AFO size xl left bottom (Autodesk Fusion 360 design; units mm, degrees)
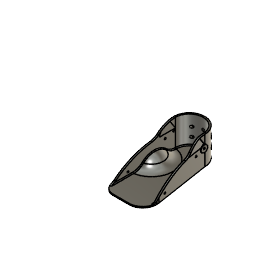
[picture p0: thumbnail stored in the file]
part number: 2025-10-02-12-56-12-317
parameter "d73" = 49
parameter "d131" = 16
sketch "Sketch1" plane through (0, 0, 0) normal (0, 0, 1) x axis (1, 0, 0)
  line L1 (28, -127.4) -> (-48, -127.4)
  line L2 (28, 0) -> (28, -127.4)
  line L3 (25, 0) -> (25, -127.4)
  line L4 (28, 0) -> (25, 0)
  line L5 (-18.603, -127.4) -> (-18.603, -115.6)
  line L6 (10.5, -127.4) -> (10.5, -109.9)
  line L7 (10.5, -127.4) -> (-18.603, -127.4)
  line L8 (36.7314, -101.9) -> (-43.9969, -101.9)
  line L9 (0, 0) -> (-28.984, 0)
  line L10 (-45, -127.4) -> (-25, 0)
  line L11 (-40.9969, -101.9) -> (-44.0794, -101.4161)
  line L12 (-48, -127.4) -> (-28, 0)
  line L13 (-43.6846, -101.9) -> (-43.6828, -102.2021)
  circle C1 centre (0, 0) radius 28
  circle C2 centre (0, 0) radius 25
  circle C3 centre (10.5, -109.9) radius 17.5
  circle C4 centre (-18.1846, -101.9) radius 22.5
  circle C5 centre (10.5, -109.9) radius 14.5
  circle C6 centre (-18.1846, -101.9) radius 25.5
  point P1 (0, 0)
  point P2 (0, 0)
  point P5 (28, 0)
  point P6 (0, 0)
  point P7 (25, 0)
  point P8 (25, -127.4)
  point P13 (-18.603, -127.4)
  point P11 (10.5, -109.9)
  point P14 (10.5, -109.9)
  point P15 (10.5, -127.4)
  point P20 (-25, 0)
  point P21 (-45, -127.4)
  point P22 (-40.9969, -101.9)
  point P10 (-18.1846, -101.9)
  point P25 (-28, 0)
  point P16 (-43.9969, -101.9)
  point P26 (-43.6828, -102.2021)
  point P27 (-43.6846, -101.9)
  point P19 (0, 0)
  coincident P1 P2
  coincident C1 P5
  tangent C1 L2
  perpendicular L1 L2
  coincident P1 P6
  vertical L3
  coincident C2 P7
  perpendicular L2 L4
  coincident L1 P8
  tangent L2 C3
  tangent L1 C3
  concentric C3 C5
  tangent L3 C5
  coincident L1 P13
  perpendicular L1 L5
  coincident P11 P14
  coincident L1 P15
  coincident C3 P15
  perpendicular L1 L6
  perpendicular L5 L8
  horizontal L9
  coincident C2 P20
  coincident L9 P20
  coincident L1 P21
  coincident L10 P22
  coincident L8 P22
  parallel L2 L3
  coincident P10 L8
  concentric C4 C6
  coincident L9 P25
  coincident C1 P25
  parallel L10 L12
  coincident P16 L12
  coincident C6 P26
  coincident L8 P27
  coincident C6 P27
  coincident P1 P19
  tangent L1 C6
  tangent C6 L12
  perpendicular L11 L12
  dimension "d2" diameter C1 = 56 (= "d57 + ( 3 * 2 ) * 1 mm")
  dimension "d4" distance P2 L1 = 127.4 (= "152.4 mm - 25 mm")
  dimension "d57" diameter C2 = 50
  dimension "d74" diameter C3 = 35
  dimension "d252" diameter C4 = 45 (= "d73 - 4 mm")
  dimension "d322" distance P8 P21 = 70
  dimension "d323" diameter C6 = 51 (= "d252 + 6 mm")
extrude "Extrude1" new body sketch "Sketch1" profile of C1 L2 L3 L4 C3 L8 L9 L10 L11 C6 L12 along normal blind 35
extrude "Extrude2" add sketch "Sketch1" profile of C1 L1 L2 C2 L3 C3 C4 C5 L5 L6 L7 L8 L10 L11 C6 L13 along normal blind 3
extrude "Extrude15" new body sketch "Sketch1" profile of C1 C2 L4 L9 along normal blind 178
combine "Combine2"
work_plane "WorkPlane1" RotateAngle -90
fillet "Fillet69" radius 1 1
sketch "Sketch23" plane through (28, 0, 0) normal (1, 0, 0) x axis (0, 1, 0)
  line L1 (-28, 78) -> (0, 35)
  line L2 (-28, 178) -> (-28, 78)
  line L3 (0, 178) -> (-28, 178)
  line L4 (0, 35) -> (0, 178)
  circle C1 centre (-3, 143) radius 1.75
  point P5 (0, 178)
  point P6 (0, 178)
  point P2 (0, 35)
  point P8 (0, 35)
  point P4 (-28, 178)
  point P3 (-28, 78)
  point P7 (-3, 143)
  horizontal L3
  perpendicular L3 L4
  coincident P5 P6
  coincident P2 P8
  parallel L2 L4
  dimension "d253" distance P4 P5 = 28
  dimension "d254" distance P3 P4 = 100
  dimension "d255" diameter C1 = 3.5
  dimension "d256" distance L3 P7 = 35
  dimension "d257" distance L2 P7 = 25
extrude "Extrude18" add sketch "Sketch23" against normal blind 3
mirror "Mirror1" mirrorStitchTolerance 0.1
sketch "Sketch24" plane through (0, 16.0046, 10.4216) normal (0, -0.838, -0.5457) x axis (1, 0, 0)
  line L1 (-25, 80.6427) -> (-25, 29.3299)
  line L2 (-28, 80.6427) -> (-25, 80.6427)
  line L3 (-28, 29.3299) -> (-28, 80.6427)
  line L4 (-25, 62.182) -> (-28, 62.182)
  line L5 (-28, 30.2476) -> (-25, 30.2476)
  line L6 (-28, 30.2476) -> (-28, 62.182)
  line L7 (-25, 62.182) -> (-25, 30.2476)
  line L8 (-25, 29.3299) -> (-28, 29.3299)
  point P6 (-28, 62.182)
  point P7 (-25, 62.182)
  point P8 (-25, 30.2476)
  point P9 (-28, 30.2476)
  coincident L3 P6
  coincident L1 P7
  perpendicular L1 L4
  coincident L1 P8
  coincident L3 P9
  perpendicular L3 L5
sketch "Sketch25" plane through (0, 0, 35) normal (0, 0, 1) x axis (-1, 0, 0)
  line L1 (24.843, -1) -> (27.843, -1)
  line L2 (29.5678, 29.0967) -> (24.843, -1)
  line L3 (32.4956, 28.637) -> (29.5678, 29.0967)
  line L4 (32.4956, 28.637) -> (27.843, -1)
  line L5 (0, 0) -> (28.984, 0)
  line L6 (43.3761, 97.9455) -> (28, 0)
  line L7 (25, 0) -> (40.9969, 101.9)
  line L8 (28, 0) -> (25, 0)
  line L9 (40.9969, 101.9) -> (43.6811, 101.4786)
  arc A1 centre (18.1846, 101.9) radius 25.5 clockwise from (43.6811, 101.4786) to (43.3761, 97.9455)
  point P5 (32.4956, 28.637)
  point P4 (29.5678, 29.0967)
  point P15 (28, 0)
  point P8 (25, 0)
  point P2 (27.843, -1)
  horizontal L1
  coincident P5 L6
  coincident P4 L7
  coincident L4 P15
  coincident L2 P8
  perpendicular L3 L4
  dimension "d280" distance P2 P5 = 30
  dimension "d281" distance L1 L5 = 1
loft "Loft1" sketch "Sketch24" + "Sketch25"
sketch "Sketch26" plane through (0, 0, 35) normal (0, 0, 1) x axis (-1, 0, 0)
  line L1 (-28, 0) -> (-28, 101.9)
  line L2 (-25, 0) -> (-28, 0)
  line L3 (-28, -1) -> (-25, -1)
  line L4 (-28, -1) -> (-28, 29)
  line L5 (-25, 29) -> (-28, 29)
  line L6 (-25, -1) -> (-25, 29)
  line L7 (-28, 101.9) -> (-25, 101.9)
  line L8 (-25, 101.9) -> (-25, 0)
  point P5 (-28, -1)
  point P6 (-28, 29)
  point P7 (-25, 29)
  coincident L1 P5
  perpendicular L1 L3
  coincident L1 P6
  coincident P7 L8
  dimension "d278" distance P5 P6 = 30
  dimension "d279" distance L2 L3 = 1
sketch "Sketch27" plane through (0, 16.0046, 10.4216) normal (0, -0.838, -0.5457) x axis (1, 0, 0)
  line L1 (28, 80.6427) -> (28, 29.3299)
  line L2 (25, 80.6427) -> (28, 80.6427)
  line L3 (25, 29.3299) -> (25, 80.6427)
  line L4 (28, 29.3299) -> (25, 29.3299)
  line L5 (28, 63.1164) -> (25, 63.1164)
  line L6 (28, 32.1164) -> (28, 63.1164)
  line L7 (28, 32.1164) -> (25, 32.1164)
  line L8 (25, 63.1164) -> (25, 32.1164)
  point P6 (25, 63.1164)
  point P7 (28, 63.1164)
  point P8 (28, 32.1164)
  point P9 (25, 32.1164)
  coincident L3 P6
  coincident L1 P7
  perpendicular L1 L5
  coincident L1 P8
  coincident L3 P9
  perpendicular L6 L7
  dimension "d282" distance P7 P8 = 31
loft "Loft2" sketch "Sketch27" + "Sketch26"
work_plane "WorkPlane4" AlongDistance 28 (= "25 mm + 3 mm")
sketch "Sketch9" plane through (0, 28, 0) normal (0, 1, 0) x axis (1, 0, 0)
  circle C1 centre (0, -16) radius 2.25
  circle C2 centre (0, -32) radius 2.25
  circle C3 centre (0, -64) radius 2.25
  circle C4 centre (0, -96) radius 2.25
  circle C5 centre (0, -80) radius 2.25
  circle C6 centre (0, -112) radius 2.25
  circle C7 centre (0, -128) radius 2.25
  circle C8 centre (0, -144) radius 2.25
  point P2 (0, -16)
  point P7 (0, 0)
  point P3 (0, -32)
  point P4 (0, -64)
  point P6 (0, -80)
  point P5 (0, -96)
  point P8 (0, -112)
  point P9 (0, -128)
  point P10 (0, -144)
  dimension "d123" diameter C1 = 4.5
  dimension "d124" diameter C2 = 4.5
  dimension "d126" diameter C3 = 4.5
  dimension "d127" diameter C4 = 4.5
  dimension "d128" diameter C5 = 4.5
  dimension "d129" distance P2 P7 = 16
  dimension "d130" distance P2 P3 = 16
  dimension "d133" distance P4 P6 = 16 (= "d131")
  dimension "d134" distance P5 P6 = 16 (= "d131")
  dimension "d291" diameter C6 = 4.5
  dimension "d292" distance P5 P8 = 16 (= "d131")
  dimension "d293" distance P8 P9 = 16 (= "d130")
  dimension "d294" diameter C7 = 4.5
  dimension "d295" diameter C8 = 4.5
  dimension "d296" distance P9 P10 = 16 (= "d131")
extrude "Extrude20" cut sketch "Sketch9" against normal blind 30
path_pattern "PathPattern3" PathPatternDelta 88.0394
fillet "Fillet51" radius 7 15
fillet "Fillet52" radius 130 130
sphere_primitive "SpherePrimitive3" Diameter 55
move_face "MoveFace3"
boundary_fill "BoundaryFill2"
offset_faces "OffsetFaces2" distance 3
shell "Shell7" innerThickness 2.99
fillet "Fillet74" radius 10 15
hole "Hole6" HoleDepth 106.033 HoleDiameter 3.5 TipAngle 118
hole "Hole7" HoleDepth 106.033 HoleDiameter 3.5 TipAngle 118
work_plane "WorkPlane5" AlongDistance 100
work_plane "WorkPlane6" AlongDistance 51.6037
fillet "Fillet76" radius 30
fillet "Fillet79" radius 25
fillet "Fillet83" radius 22
fillet "Fillet85" radius 30 30
fillet "Fillet86" radius 45
split "Split1"
work_plane "WorkPlane7" AlongDistance -28 (= "-( 56 / 2 ) * 1 mm")
sketch "Sketch35" plane through (-28, 0, 0) normal (1, 0, 0) x axis (0, 1, 0)
  circle C1 centre (-2.7874, 31.4508) radius 6
  dimension "d426" diameter C1 = 12
extrude "Extrude22" add sketch "Sketch35" against normal blind 2
fillet "Fillet87" radius 35
sketch "Sketch33" plane through (27.99, 0, 0) normal (1, 0, 0) x axis (0, 1, 0)
  line L1 (0, 139.3302) -> (0, 52.395)
  line L2 (0, 175.01) -> (0, 146.6698)
  line L3 (-11.056, 175.01) -> (0, 175.01)
  line L4 (-25.01, 78.8877) -> (-25.01, 161.056)
  line L5 (-15.1078, 63.6808) -> (-25.01, 78.8877)
  line L6 (-16.1988, 60.7566) -> (-15.1078, 63.6808)
  line L7 (2, 178) -> (28, 178)
  arc A1 centre (7.4005, 86.6037) radius 35 clockwise from (0, 52.395) to (-16.1988, 60.7566)
  arc A2 centre (-3, 143) radius 4.74 clockwise from (0, 139.3302) to (0, 146.6698)
  arc A3 centre (2, 148) radius 30 clockwise from (-25.01, 161.056) to (-11.056, 175.01)
  circle C1 centre (-3, 128) radius 1.5
  circle C2 centre (-3, 98) radius 1.7185
  circle C3 centre (-3, 32) radius 1.75
  point P16 (-3, 128)
  point P17 (-3, 98)
  point P18 (-3, 32)
  vertical P16 P17
  vertical P17 P18
  dimension "d413" diameter C1 = 3
  dimension "d414" distance P16 P17 = 30
  dimension "d415" diameter C3 = 3.5
  dimension "d416" distance P17 P18 = 66
  dimension "d417" distance P16 L7 = 50
  dimension "d418" distance L1 P16 = 3
extrude "Extrude21" cut sketch "Sketch33" profile of C1 C2 C3 against normal blind 133.937
fillet "Fillet88" radius 36
sketch "Sketch37" plane through (-28, 0, 0) normal (1, 0, 0) x axis (0, 1, 0)
fillet "Fillet98" radius 48
fillet "Fillet99" radius 48
sketch "Sketch38" plane through (-28, 0, 0) normal (1, 0, 0) x axis (0, 1, 0)
  line L1 (-5.5406, 132.8689) -> (0, 132.8689)
  line L2 (-5.5406, 93.572) -> (-5.5406, 132.8689)
  line L3 (0, 93.572) -> (-5.5406, 93.572)
  line L4 (0, 132.8689) -> (0, 93.572)
  horizontal L1
  vertical L2
  horizontal L3
  vertical L4
extrude "Extrude24" add sketch "Sketch38" along normal blind 1 and against normal blind 2
fillet "Fillet91" radius 2 2 2 2
fillet "Fillet92" radius 0.5
extrude "Extrude25" cut sketch "Sketch33" profile of C1 C2 against normal blind 188.494
work_plane "WorkPlane8" AlongDistance 178
sketch "Sketch39" plane through (0, 0, 178) normal (0, 0, 1) x axis (1, 0, 0)
  line L1 (-25, 0) -> (25, 0)
  line L2 (30, 0) -> (25, 0)
  line L3 (-32, 0) -> (-25, 0)
  arc A1 centre (0, 10.2) radius 29.8 clockwise from (-28, 0) to (28, 0)
  point P7 (-28, 0)
  horizontal L1
  parallel L1 L2
  parallel L1 L3
  coincident L3 P7
revolve "Revolve2" sketch "Sketch39" AlongAngle -30
fillet "Fillet95" radius 20 20
fillet "Fillet97" radius 1.5
fillet "Fillet100" radius 0.2
mirror "Mirror4" mirrorStitchTolerance 0.1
